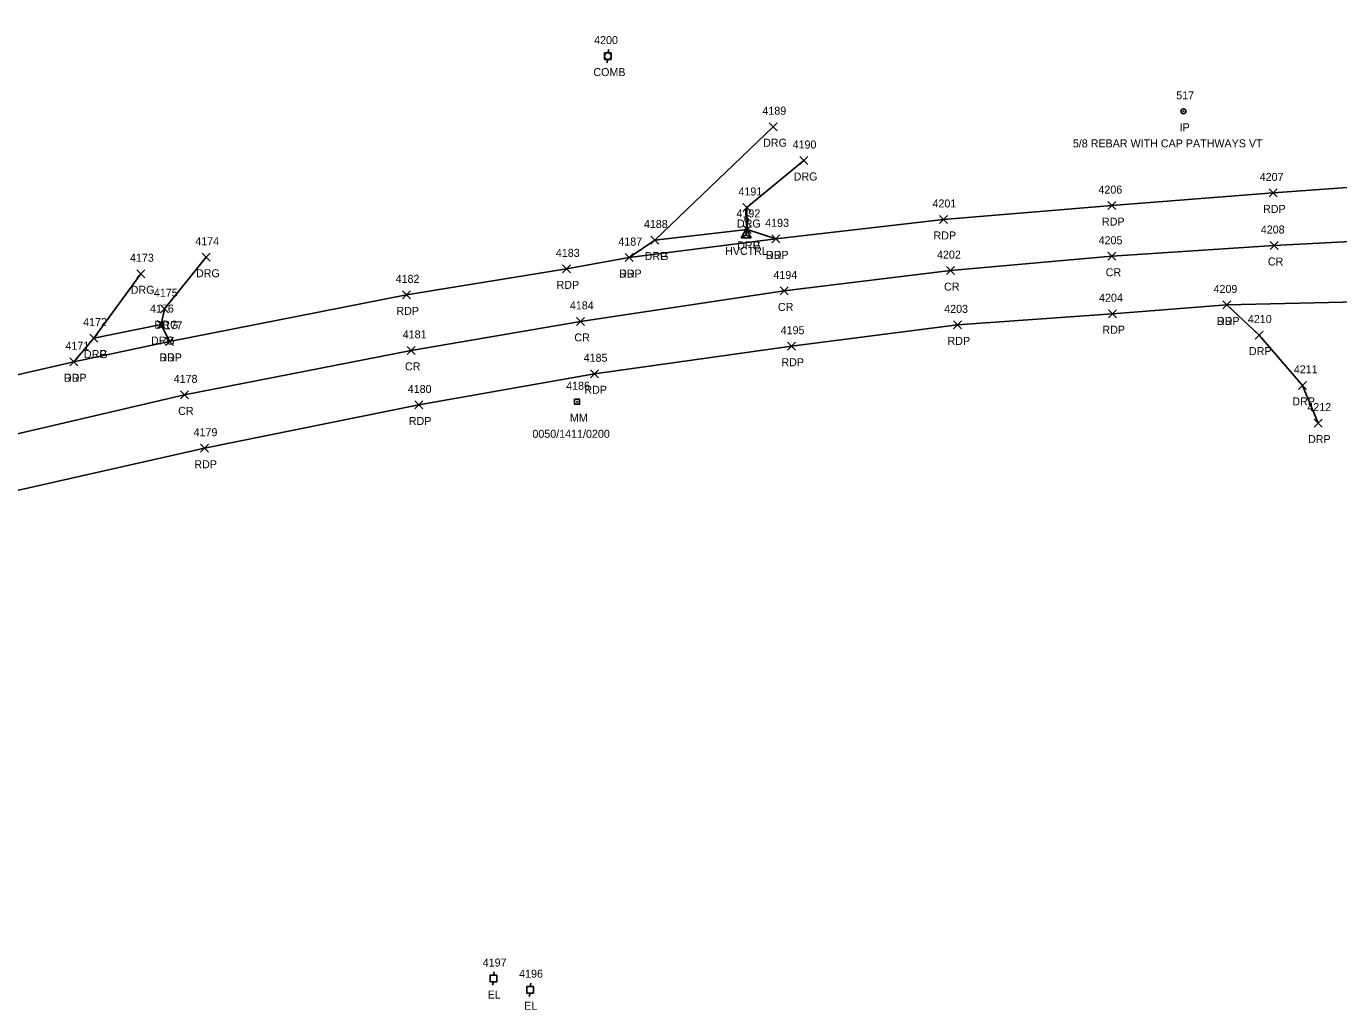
# Model space of a CAD drawing. Extents: x 1690689 to 1696275, y 438760 to 444007.
# Drawn here: x 1693779.1 to 1694107.1, y 443379.3 to 443625 of the extents above; entities that cross this region are included whole.
import ezdxf

# ---------------------------------------------------------------- set-up
doc = ezdxf.new("R2010")
doc.units = 0
for name, color, linetype in [('C_A', 7, 'Continuous'), ('C_I', 7, 'Continuous'), ('CPSM', 7, 'Continuous'), ('M_A', 7, 'Continuous'), ('M_C', 7, 'Continuous'), ('M_I', 7, 'Continuous'), ('MPIR', 7, 'Continuous'), ('P_A', 7, 'Continuous'), ('P_I', 7, 'Continuous'), ('P_TIC', 7, 'Continuous'), ('PET', 7, 'Continuous'), ('PRC', 7, 'Continuous'), ('R_A', 7, 'Continuous'), ('R_I', 7, 'Continuous'), ('R_TIC', 7, 'Continuous'), ('RDG', 7, 'Continuous'), ('RDP', 7, 'Continuous'), ('S_A', 7, 'Continuous'), ('S_C', 7, 'Continuous'), ('S_I', 7, 'Continuous'), ('SRM', 7, 'Continuous'), ('U_A', 7, 'Continuous'), ('U_I', 7, 'Continuous'), ('UEPT', 7, 'Continuous'), ('UP', 7, 'Continuous')]:
    doc.layers.add(name, color=color, linetype=linetype)

msp = doc.modelspace()

# ---------------------------------------------------------------- linework, layer by layer
at = {"layer": 'CPSM'}
for p, q in [((1693957.79, 443572.14), (1693959.04, 443574.3)), ((1693957.79, 443572.14), (1693959.04, 443572.86)), ((1693957.79, 443572.14), (1693960.29, 443572.14)), ((1693960.29, 443572.14), (1693959.04, 443574.3)), ((1693959.04, 443572.86), (1693959.04, 443574.3)), ((1693959.04, 443572.86), (1693959.04, 443572.86)), ((1693959.04, 443572.86), (1693960.29, 443572.14))]:
    msp.add_line(p, q, dxfattribs=at)
at = {"layer": 'MPIR'}
for radius in [0.625, 0.0833]:
    msp.add_circle((1694068.26, 443603.73), radius, dxfattribs=at)
at = {"layer": 'P_TIC'}
for points in [[(1694089.66, 443582.35), (1694091.66, 443584.35)], [(1694091.66, 443582.35), (1694089.66, 443584.35)], [(1694049.41, 443579.18), (1694051.41, 443581.18)], [(1694051.41, 443579.18), (1694049.41, 443581.18)], [(1694007.33, 443575.72), (1694009.33, 443577.72)], [(1694009.33, 443575.72), (1694007.33, 443577.72)], [(1693965.45, 443570.88), (1693967.45, 443572.88)], [(1693967.45, 443570.88), (1693965.45, 443572.88)], [(1694089.93, 443569.21), (1694091.93, 443571.21)], [(1694091.93, 443569.21), (1694089.93, 443571.21)], [(1693913.15, 443563.38), (1693915.15, 443565.38)], [(1693915.15, 443563.38), (1693913.15, 443565.38)], [(1693928.75, 443566.2), (1693930.75, 443568.2)], [(1693930.75, 443566.2), (1693928.75, 443568.2)], [(1694049.41, 443566.52), (1694051.41, 443568.52)], [(1694051.41, 443566.52), (1694049.41, 443568.52)], [(1694009.03, 443562.94), (1694011.03, 443564.94)], [(1694011.03, 443562.94), (1694009.03, 443564.94)], [(1693873.12, 443556.88), (1693875.12, 443558.88)], [(1693875.12, 443556.88), (1693873.12, 443558.88)], [(1693967.51, 443557.86), (1693969.51, 443559.86)], [(1693969.51, 443557.86), (1693967.51, 443559.86)], [(1694078.13, 443554.36), (1694080.13, 443556.36)], [(1694080.13, 443554.36), (1694078.13, 443556.36)], [(1693916.65, 443550.25), (1693918.65, 443552.25)], [(1693918.65, 443550.25), (1693916.65, 443552.25)], [(1694049.52, 443552.17), (1694051.52, 443554.17)], [(1694051.52, 443552.17), (1694049.52, 443554.17)], [(1694010.83, 443549.38), (1694012.83, 443551.38)], [(1694012.83, 443549.38), (1694010.83, 443551.38)], [(1693813.89, 443545.26), (1693815.89, 443547.26)], [(1693815.89, 443545.26), (1693813.89, 443547.26)], [(1693969.32, 443544.04), (1693971.32, 443546.04)], [(1693971.32, 443544.04), (1693969.32, 443546.04)], [(1693874.33, 443543.01), (1693876.33, 443545.01)], [(1693876.33, 443543.01), (1693874.33, 443545.01)], [(1693790.06, 443540.17), (1693792.06, 443542.17)], [(1693792.06, 443540.17), (1693790.06, 443542.17)], [(1693920.1, 443537.16), (1693922.1, 443539.16)], [(1693922.1, 443537.16), (1693920.1, 443539.16)], [(1693817.66, 443531.89), (1693819.66, 443533.89)], [(1693819.66, 443531.89), (1693817.66, 443533.89)], [(1693876.23, 443529.37), (1693878.23, 443531.37)], [(1693878.23, 443529.37), (1693876.23, 443531.37)], [(1693822.64, 443518.56), (1693824.64, 443520.56)], [(1693824.64, 443518.56), (1693822.64, 443520.56)]]:
    msp.add_lwpolyline(points, dxfattribs=at)
at = {"layer": 'PET'}
for points in [[(1693397.96, 443433.36), (1693480.89, 443455.03), (1693514.01, 443463.95), (1693603.18, 443490.24), (1693652.52, 443505.09), (1693712.14, 443521.54), (1693763.48, 443534.79), (1693791.06, 443541.17), (1693814.89, 443546.26), (1693874.12, 443557.88), (1693914.15, 443564.38), (1693929.75, 443567.2), (1693966.45, 443571.88), (1694008.33, 443576.72), (1694050.41, 443580.18), (1694090.66, 443583.35), (1694131.29, 443586.28), (1694184.33, 443593.61), (1694246.45, 443596.98), (1694283.26, 443600.85), (1694305.23, 443603.13), (1694323.85, 443600.59), (1694399.36, 443604.74), (1694794.31, 443624.99)], [(1693402.37, 443405.33), (1693529.25, 443439.82), (1693551.29, 443445.75), (1693583.21, 443455.14), (1693612.15, 443463.58), (1693659.65, 443478.17), (1693719.32, 443494.83), (1693769.41, 443507.35), (1693823.64, 443519.56), (1693877.23, 443530.37), (1693921.1, 443538.16), (1693970.32, 443545.04), (1694011.83, 443550.38), (1694050.52, 443553.17), (1694079.13, 443555.36), (1694158.97, 443557.19), (1694248.34, 443555.93), (1694367.36, 443558.71), (1694412.77, 443560.7), (1694744.37, 443577.01)]]:
    msp.add_lwpolyline(points, dxfattribs=at)
at = {"layer": 'PRC'}
msp.add_lwpolyline([(1693400.05, 443418.88), (1693519.35, 443451.5), (1693607.47, 443477.56), (1693655.98, 443491.5), (1693716.33, 443508.24), (1693766.13, 443520.65), (1693818.66, 443532.89), (1693875.33, 443544.01), (1693917.65, 443551.25), (1693968.51, 443558.86), (1694010.03, 443563.94), (1694050.41, 443567.52), (1694090.93, 443570.21), (1694159.42, 443573.76), (1694248.41, 443577.88), (1694744.61, 443600.37)], dxfattribs=at)
at = {"layer": 'R_TIC'}
for points in [[(1693964.76, 443598.89), (1693966.76, 443600.89)], [(1693966.76, 443598.89), (1693964.76, 443600.89)], [(1693972.39, 443590.45), (1693974.39, 443592.45)], [(1693974.39, 443590.45), (1693972.39, 443592.45)], [(1693958.21, 443578.71), (1693960.21, 443580.71)], [(1693960.21, 443578.71), (1693958.21, 443580.71)], [(1693958.27, 443573.24), (1693960.27, 443575.24)], [(1693960.27, 443573.24), (1693958.27, 443575.24)], [(1693958.27, 443573.24), (1693960.27, 443575.24)], [(1693960.27, 443573.24), (1693958.27, 443575.24)], [(1693935.15, 443570.58), (1693937.15, 443572.58)], [(1693937.15, 443570.58), (1693935.15, 443572.58)], [(1693935.15, 443570.58), (1693937.15, 443572.58)], [(1693937.15, 443570.58), (1693935.15, 443572.58)], [(1693965.45, 443570.88), (1693967.45, 443572.88)], [(1693967.45, 443570.88), (1693965.45, 443572.88)], [(1693823.06, 443566.28), (1693825.06, 443568.28)], [(1693825.06, 443566.28), (1693823.06, 443568.28)], [(1693928.75, 443566.2), (1693930.75, 443568.2)], [(1693930.75, 443566.2), (1693928.75, 443568.2)], [(1693806.74, 443562.15), (1693808.74, 443564.15)], [(1693808.74, 443562.15), (1693806.74, 443564.15)], [(1694078.13, 443554.36), (1694080.13, 443556.36)], [(1694080.13, 443554.36), (1694078.13, 443556.36)], [(1693812.71, 443553.41), (1693814.71, 443555.41)], [(1693814.71, 443553.41), (1693812.71, 443555.41)], [(1693811.81, 443549.46), (1693813.81, 443551.46)], [(1693813.81, 443549.46), (1693811.81, 443551.46)], [(1693811.81, 443549.46), (1693813.81, 443551.46)], [(1693813.81, 443549.46), (1693811.81, 443551.46)], [(1693795.06, 443546.08), (1693797.06, 443548.08)], [(1693797.06, 443546.08), (1693795.06, 443548.08)], [(1693795.06, 443546.08), (1693797.06, 443548.08)], [(1693797.06, 443546.08), (1693795.06, 443548.08)], [(1693813.89, 443545.26), (1693815.89, 443547.26)], [(1693815.89, 443545.26), (1693813.89, 443547.26)], [(1694086.14, 443546.84), (1694088.14, 443548.84)], [(1694088.14, 443546.84), (1694086.14, 443548.84)], [(1693790.06, 443540.17), (1693792.06, 443542.17)], [(1693792.06, 443540.17), (1693790.06, 443542.17)], [(1694096.97, 443534.27), (1694098.97, 443536.27)], [(1694098.97, 443534.27), (1694096.97, 443536.27)], [(1694100.91, 443524.84), (1694102.91, 443526.84)], [(1694102.91, 443524.84), (1694100.91, 443526.84)]]:
    msp.add_lwpolyline(points, dxfattribs=at)
at = {"layer": 'RDG'}
for points in [[(1693936.15, 443571.58), (1693965.76, 443599.89)], [(1693973.39, 443591.45), (1693959.21, 443579.71), (1693959.27, 443574.24)], [(1693824.06, 443567.28), (1693813.71, 443554.41), (1693812.81, 443550.46)], [(1693796.06, 443547.08), (1693807.74, 443563.15)]]:
    msp.add_lwpolyline(points, dxfattribs=at)
at = {"layer": 'RDP'}
for points in [[(1693929.75, 443567.2), (1693936.15, 443571.58), (1693959.27, 443574.24), (1693966.45, 443571.88)], [(1694079.13, 443555.36), (1694087.14, 443547.84), (1694097.97, 443535.27), (1694101.91, 443525.84)], [(1693791.06, 443541.17), (1693796.06, 443547.08), (1693812.81, 443550.46), (1693814.89, 443546.26)]]:
    msp.add_lwpolyline(points, dxfattribs=at)
at = {"layer": 'SRM'}
msp.add_lwpolyline([(1693916.15, 443531.79), (1693917.4, 443531.79), (1693917.4, 443530.54), (1693916.15, 443530.54)], close=True, dxfattribs=at)
msp.add_circle((1693916.78, 443531.17), 0.0833, dxfattribs=at)
at = {"layer": 'UEPT'}
for p, q in [((1693896.05, 443388.74), (1693895.89, 443387.91)), ((1693895.05, 443386.24), (1693895.05, 443387.91)), ((1693895.05, 443387.91), (1693896.72, 443387.91)), ((1693896.72, 443386.24), (1693895.05, 443386.24)), ((1693895.64, 443385.41), (1693895.89, 443386.24)), ((1693895.89, 443387.07), (1693895.89, 443387.07)), ((1693896.72, 443387.91), (1693896.72, 443386.24)), ((1693904.2, 443383.43), (1693904.2, 443385.1)), ((1693904.2, 443385.1), (1693905.87, 443385.1)), ((1693905.2, 443385.93), (1693905.04, 443385.1)), ((1693905.87, 443385.1), (1693905.87, 443383.43)), ((1693905.87, 443383.43), (1693904.2, 443383.43)), ((1693904.79, 443382.6), (1693905.04, 443383.43)), ((1693905.04, 443384.27), (1693905.04, 443384.27))]:
    msp.add_line(p, q, dxfattribs=at)
at = {"layer": 'UP'}
for p, q in [((1693923.61, 443616.7), (1693923.61, 443618.37)), ((1693923.61, 443618.37), (1693925.28, 443618.37)), ((1693924.7, 443619.2), (1693924.45, 443618.37)), ((1693925.28, 443618.37), (1693925.28, 443616.7)), ((1693925.28, 443616.7), (1693923.61, 443616.7)), ((1693924.2, 443615.87), (1693924.45, 443616.7)), ((1693924.45, 443617.54), (1693924.45, 443617.54))]:
    msp.add_line(p, q, dxfattribs=at)
msp.add_circle((1693924.45, 443617.54), 0.833, dxfattribs=at)

# ---------------------------------------------------------------- texts
at = {"layer": 'C_A'}
msp.add_text('HVCTRL', height=2, dxfattribs=at).set_placement((1693953.74, 443567.86))
at = {"layer": 'C_I'}
msp.add_text('6', height=2, dxfattribs=at).set_placement((1693958.42, 443575.86))
at = {"layer": 'M_A'}
msp.add_text('IP', height=2, dxfattribs=at).set_placement((1694067.31, 443598.73))
at = {"layer": 'M_C'}
msp.add_text('5/8 REBAR WITH CAP PATHWAYS VT', height=2, dxfattribs=at).set_placement((1694040.63, 443594.73))
at = {"layer": 'M_I'}
msp.add_text('517', height=2, dxfattribs=at).set_placement((1694066.46, 443606.73))
at = {"layer": 'P_A'}
for s, p in [('RDP', (1694088.15, 443578.35)), ('RDP', (1694047.9, 443575.18)), ('RDP', (1694005.82, 443571.72)), ('RDP', (1693963.94, 443566.88)), ('CR', (1694089.36, 443565.21)), ('RDP', (1693927.24, 443562.2)), ('CR', (1694048.84, 443562.52)), ('RDP', (1693911.64, 443559.38)), ('CR', (1694008.46, 443558.94)), ('CR', (1693966.94, 443553.86)), ('RDP', (1693871.61, 443552.88)), ('RDP', (1694076.62, 443550.36)), ('RDP', (1694048.01, 443548.17)), ('CR', (1693916.08, 443546.25)), ('RDP', (1694009.32, 443545.38)), ('RDP', (1693812.38, 443541.26)), ('CR', (1693873.76, 443539.01)), ('RDP', (1693967.81, 443540.04)), ('RDP', (1693788.55, 443536.17)), ('RDP', (1693918.58, 443533.16)), ('CR', (1693817.1, 443527.89)), ('RDP', (1693874.72, 443525.37)), ('RDP', (1693821.13, 443514.56))]:
    msp.add_text(s, height=2, dxfattribs=at).set_placement(p)
at = {"layer": 'P_I'}
for s, p in [('4207', (1694087.32, 443586.35)), ('4206', (1694047.02, 443583.18)), ('4201', (1694005.56, 443579.72)), ('4193', (1693963.76, 443574.88)), ('4208', (1694087.59, 443573.21)), ('4187', (1693927.06, 443570.2)), ('4205', (1694047.07, 443570.52)), ('4183', (1693911.46, 443567.38)), ('4202', (1694006.69, 443566.94)), ('4182', (1693871.43, 443560.88)), ('4194', (1693965.82, 443561.86)), ('4209', (1694075.78, 443558.36)), ('4184', (1693914.96, 443554.25)), ('4204', (1694047.18, 443556.17)), ('4203', (1694008.49, 443553.38)), ('4177', (1693812.2, 443549.26)), ('4181', (1693873.2, 443547.01)), ('4195', (1693967.63, 443548.04)), ('4171', (1693788.94, 443544.17)), ('4185', (1693918.4, 443541.16)), ('4178', (1693815.97, 443535.89)), ('4180', (1693874.45, 443533.37)), ('4179', (1693820.94, 443522.56))]:
    msp.add_text(s, height=2, dxfattribs=at).set_placement(p)
at = {"layer": 'R_A'}
for s, p in [('DRG', (1693963.25, 443594.89)), ('DRG', (1693970.88, 443586.45)), ('DRG', (1693956.7, 443574.71)), ('DRG', (1693956.76, 443569.24)), ('DRP', (1693956.76, 443569.24)), ('DRP', (1693963.94, 443566.88)), ('DRG', (1693933.64, 443566.58)), ('DRP', (1693933.64, 443566.58)), ('DRG', (1693821.55, 443562.28)), ('DRP', (1693927.24, 443562.2)), ('DRG', (1693805.23, 443558.15)), ('DRP', (1694076.62, 443550.36)), ('DRG', (1693811.2, 443549.41)), ('DRG', (1693810.3, 443545.46)), ('DRP', (1693810.3, 443545.46)), ('DRG', (1693793.55, 443542.08)), ('DRP', (1693793.55, 443542.08)), ('DRP', (1693812.38, 443541.26)), ('DRP', (1694084.62, 443542.84)), ('DRP', (1693788.55, 443536.17)), ('DRP', (1694095.46, 443530.27)), ('DRP', (1694099.4, 443520.84))]:
    msp.add_text(s, height=2, dxfattribs=at).set_placement(p)
at = {"layer": 'R_I'}
for s, p in [('4189', (1693963.06, 443602.89)), ('4190', (1693970.61, 443594.45)), ('4191', (1693957.08, 443582.71)), ('4192', (1693956.58, 443577.24)), ('4192', (1693956.58, 443577.24)), ('4188', (1693933.46, 443574.58)), ('4188', (1693933.46, 443574.58)), ('4193', (1693963.76, 443574.88)), ('4174', (1693821.37, 443570.28)), ('4187', (1693927.06, 443570.2)), ('4173', (1693805.05, 443566.15)), ('4175', (1693811.02, 443557.41)), ('4209', (1694075.78, 443558.36)), ('4176', (1693810.06, 443553.46)), ('4176', (1693810.06, 443553.46)), ('4210', (1694084.36, 443550.84)), ('4172', (1693793.36, 443550.08)), ('4172', (1693793.36, 443550.08)), ('4177', (1693812.2, 443549.26)), ('4171', (1693788.94, 443544.17)), ('4211', (1694095.84, 443538.27)), ('4212', (1694099.21, 443528.84))]:
    msp.add_text(s, height=2, dxfattribs=at).set_placement(p)
at = {"layer": 'S_A'}
msp.add_text('MM', height=2, dxfattribs=at).set_placement((1693914.97, 443526.17))
at = {"layer": 'S_C'}
msp.add_text('0050/1411/0200', height=2, dxfattribs=at).set_placement((1693905.6, 443522.17))
at = {"layer": 'S_I'}
msp.add_text('4186', height=2, dxfattribs=at).set_placement((1693914.03, 443534.17))
at = {"layer": 'U_A'}
for s, p in [('COMB', (1693920.83, 443612.54)), ('EL', (1693894.42, 443382.07)), ('EL', (1693903.57, 443379.27))]:
    msp.add_text(s, height=2, dxfattribs=at).set_placement(p)
at = {"layer": 'U_I'}
for s, p in [('4200', (1693921.02, 443620.54)), ('4197', (1693893.19, 443390.07)), ('4196', (1693902.29, 443387.27))]:
    msp.add_text(s, height=2, dxfattribs=at).set_placement(p)

doc.saveas('drawing.dxf')
